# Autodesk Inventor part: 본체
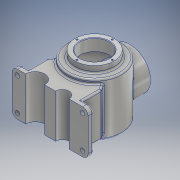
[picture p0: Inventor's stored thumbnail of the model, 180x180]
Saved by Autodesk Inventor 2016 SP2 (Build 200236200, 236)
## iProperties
Created: 2018-08
Part Number: 본체
Material: 알루미늄 6061
Document SubType Name: Modeling
Designer: Administrator
Density: 2.7 g/cm^3
Appearance: 알루미늄 - 평지
Mass: 1940.07 g
Surface Area: 1087.3 cm^2
Volume: 718.546 cm^3
Author: Administrator
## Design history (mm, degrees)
sketch "스케치1"
  geometry: L1 (0, 11.794)-(0, -11.759); L2 (-70, -11.759)-(-70, -1.759); L3 (-70, -1.759)-(-50, -1.759); L4 (-50, 32.882)-(-28.496, 63.592); L5 (-50, -1.759)-(-50, 32.882); L6 (0, 11.794)-(0, 104.496); L7 (-28.496, 63.592)-(0, 63.592); L8 (70, -11.759)-(70, -1.759); L9 (70, -1.759)-(50, -1.759); L10 (50, 32.882)-(28.496, 63.592); L11 (50, -1.759)-(50, 32.882); L12 (28.496, 63.592)-(0, 63.592); L13 (-70, -11.759)-(-45, -11.759); L14 (-10, -11.759)-(0, -11.759); L15 (70, -11.759)-(35, -11.759); L16 (10, -11.759)-(0, -11.759); A1 r 17.5 centre (-27.5, -11.759) between (-10, -11.759) and (-45, -11.759); A2 r 12.5 centre (22.5, -11.759) between (35, -11.759) and (10, -11.759); 1 further point
  constraints: 32 end point, 5 symmetric about line, 4 point on circle, 4 vertical, 2 centre point, 2 horizontal, 2 perpendicular, 2 point on line
  dimensions: "d0" = 20 distance of L2.end L3.end; "d1" = 70 distance of L1.end L2.start; "d2" = 10 distance of L2.start L2.end; "d3" = 35 deg angle of L2 L4; "d4" = 35 diameter of A1; "d5" = 27.5 distance from line of L1 A1.centre; "d81" = 25 diameter of A2
extrude "돌출1" new body sketch "스케치1" stored distance "d6" = 80; taper "d7" = 0 deg
sketch "스케치2"
  geometry: L1 (-11.759, -40)-(-11.759, 40) reference; L2 (-11.759, 40)-(-1.759, 40) reference; L3 (70.241, 57.703)-(70.241, -60); L4 (70.241, 60)-(106.241, 60); L5 (106.241, 60)-(106.241, 48); L6 (106.241, 48)-(120.241, 48); L7 (120.241, 48)-(120.241, -48.671); L8 (32.882, 40)-(63.592, 40) reference; L9 (70.241, 57.703)-(70.241, 60); A1 r 116 centre (70.241, 56) between (70.241, -60) and (120.241, -48.671); 1 further point
  constraints: 12 end point, 3 perpendicular, 2 point on circle, 2 point on line, 2 vertical, 1 centre point, 1 horizontal
  dimensions: "d27" = 82 distance between parallel lines of L1 L3; "d28" = 8 distance between parallel lines of L8 L6; "d29" = 36 distance of L4.start L4.end; "d30" = 12 distance of L4.end L5.end; "d31" = 50 distance between parallel lines of L3 L7; "d33" = 116 radius of A1
revolve "회전1" sketch "스케치2" stored, may be unused: angle "d34" = 90 deg
sketch "스케치3"
  geometry: 1 further point
node "작업 평면2"
sketch "스케치4"
  geometry: L1 (-85, 8)-(15, 8) reference; C1 r 38 at (-35, -42); 1 further point
  constraints: 1 centre point, 1 vertical alignment
  dimensions: "d83" = 76 diameter of C1; "d84" = 50 distance from line of L1 C1.centre
extrude "돌출2" join sketch "스케치4" distance "d38" = 65; taper "d39" = 0 deg
sketch "스케치5"
  geometry: L1 (-71, 20)-(1, 20) reference; L2 (-85, -88.671)-(15, -88.671) reference; L3 (-85, 8)-(15, 8) reference; L4 (-77.398, 0)-(-77.398, -80) reference; L5 (7.398, 0)-(-77.398, 0) reference; L6 (7.398, -80)-(7.398, 0) reference; L7 (-77.398, -80)-(7.398, -80) reference; C1 r 27 at (-35, -42); 2 further points
  constraints: 1 centre point, 1 other
  dimensions: "d85" = 54 diameter of C1; "d87" = 50 distance from line of L3 C1.centre
extrude "돌출3" cut sketch "스케치5" distance "d41" = 65; taper "d42" = 0 deg
sketch "스케치6"
  geometry: L1 (70.241, 60)-(70.241, -50) reference; L2 (34.241, 60)-(106.241, 60) reference; L3 (97.241, 60)-(97.241, 38); L4 (97.241, 38)-(110.241, 38); L5 (110.241, 38)-(110.241, -42.163); L6 (97.241, 60)-(70.241, 60); A1 r 116 centre (70.241, 56) between (20.241, -48.671) and (120.241, -48.671) reference; A2 r 106 centre (70.241, 56) between (70.241, -50) and (110.241, -42.163); 1 further point
  constraints: 10 end point, 3 vertical, 2 perpendicular, 2 point on circle, 1 centre point, 1 horizontal, 1 midpoint, 1 point on line
  dimensions: "d43" = 10 radial gap between concentric circles of A1 A2; "d44" = 27 distance between parallel lines of L1 L3; "d46" = 22 distance of L3.start L3.end
revolve "회전2" sketch "스케치6" stored, may be unused: angle "d47" = 90 deg
sketch "스케치7"
  geometry: 1 further point
chamfer "모따기1" distance "d48" = 1; stored, may be unused: second distance "d49" = 2, angle "d50" = 45 deg
fillet "모깎기1" dims "d51" = 3
chamfer "모따기2" distance "d52" = 1; stored, may be unused: second distance "d53" = 2, angle "d54" = 45 deg
sketch "스케치8"
  geometry: 1 further point
fillet "모깎기2" dims "d55" = 10
sketch "스케치9"
  geometry: C1 r 4 at (-110, 10); C2 r 4 at (-110, 70); C3 r 4 at (10, 70); C4 r 4 at (10, 10); A1 r 10 centre (-110, 10) between (-120, 10) and (-110, 0) reference; A2 r 10 centre (-110, 70) between (-110, 80) and (-120, 70) reference; A3 r 10 centre (10, 70) between (20, 70) and (10, 80) reference; A4 r 10 centre (10, 10) between (10, 0) and (20, 10) reference; 1 further point
  constraints: 4 centre point, 4 coincident
  dimensions: "d56" = 8 diameter of C1; "d57" = 8 diameter of C2; "d58" = 8 diameter of C3
extrude "돌출4" cut sketch "스케치9" distance "d59" = 65; taper "d60" = 0 deg
fillet "모깎기3" dims "d61" = 3
node "작업 평면3"
sketch "스케치10"
  geometry: C1 r 50 at (0, 70.241) reference; C2 r 32.5 at (0, 70.241); 1 further point
  constraints: 1 centre point, 1 coincident, 1 other
  dimensions: "d90" = 65 diameter of C2
sketch "스케치11"
  geometry: C1 r 27 at (0, 0) reference; A1 r 32.5 centre (0, 0) between (0, 32.5) and (32.5, 0); 3 further points
  constraints: 4 point on circle, 1 centre point, 1 coincident
  dimensions: "d63" = 65 diameter of A1
hole "구멍1" sketch "스케치11" at (0, 32.5), (32.5, 0), (0, -32.5), (-32.5, 0) diameter "d64" = 3.242; stored, may be unused: countersink angle "d68" = 90 deg, drill point angle "d70" = 118 deg; dims "d65" = 8, "d66" = 4, "d67" = 2, "d69" = 10
sketch "스케치12"
  geometry: C1 r 27 at (0, 2) reference; A1 r 32.5 centre (0, 2) between (32.5, 2) and (0, -30.5); 2 further points
  constraints: 4 point on circle, 1 centre point, 1 coincident
  dimensions: "d89" = 65 diameter of A1
hole "구멍2" sketch "스케치12" at (32.5, 2), (0, -30.5), (-32.5, 2), (0, 34.5) diameter "d72" = 3.242; stored, may be unused: countersink angle "d76" = 90 deg, drill point angle "d78" = 118 deg; dims "d73" = 8, "d74" = 4, "d75" = 2, "d77" = 10
feature "엠보싱1" dims "d0" = 20, "d1" = 70, "d2" = 10, "d3" = 35 deg, "d4" = 35, "d5" = 27.5, "d27" = 82, "d79" = 0.5, "d80" = 0, "d81" = 25
fillet "모깎기4" dims "d88" = 3
node "솔리드1"
node "투영된 루프1"
other parameters: "d36" = -82, "d62" = 38.75
